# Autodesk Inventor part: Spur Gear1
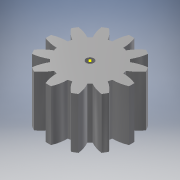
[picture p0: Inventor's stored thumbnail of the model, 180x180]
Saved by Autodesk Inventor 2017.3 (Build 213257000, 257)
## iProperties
Created: 2020-03
Part Number: Spur Gear1
Material: Steel
Document SubType Name: Modeling
Designer: Tim_G
Categories: <?xml version="1.0" encoding="UTF-16"?> <MemberInstance><Categories><FamilyTemplate><FamilyTemplateParameter ValueType="xs:double" Id="1" ObjectReferenceKey="da
Density: 1 g/cm^3
Appearance: Steel
CustomPartVersion: 1
Author: Tim_G
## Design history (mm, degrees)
sketch "Sketch1"
  geometry: C1 r 10.661 at (0, 0)
  constraints: 1 centre point
  dimensions: "d0" = 21.3211 diameter of C1 (= da_da)
extrude "Extrusion1" new body sketch "Sketch1" distance "d1" = 13 (= da_b); taper "d2" = 0 deg
workplane "Work Plane2"
sketch "Sketch2"
  geometry: C1 r 10.661 at (0, 0) reference; C2 r 9.138 at (0, 0)
  constraints: 1 centre point, 1 coincident
  dimensions: "d3" = 18.27523 diameter of C2 (= da_dw)
feature "Pitch Diameter" sketch "Sketch2" dims "d4" = 10, "d5" = 0
workplane "Work Plane8"
workplane "Work Plane9"
feature "Spur Gear" dims "da_b" = 13, "da_d" = 18.27523, "da_aw" = 28.17431, "da_da" = 21.3211, "da_df" = 14.46789, "da_dw" = 18.27523, angle "da_beta" = 0 deg, "da_lefttooth" = 0, "da_righttooth" = 0
sketch "Sketch3"
  geometry: 1 further point
sketch "Sketch4"
  geometry: C1 r 1 at (0, 0); 1 further point
  constraints: 1 centre point, 1 coincident
  dimensions: "d49" = 2 diameter of C1
extrude "Extrusion2" cut sketch "Sketch4" distance "d50" = 13; taper "d51" = 0 deg
body "Solid1"
body "Srf1"
other parameters: "d16" = 28.17431 (= da_aw), "d17" = 0, "d34" = 15 deg (computed from da_z), "d39" = 0, "d41" = 0, "d43" = 28.17431 (= da_aw), "d46" = 28.17431 (= da_aw), "d47" = 0, "d48" = 0
